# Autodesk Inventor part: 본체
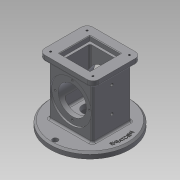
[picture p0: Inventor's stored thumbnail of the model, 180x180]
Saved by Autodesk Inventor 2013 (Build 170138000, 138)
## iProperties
Created: 2019-08
Part Number: 본체
Material: 일반
Document SubType Name: Modeling
Designer: Administrator
Density: 1 g/cm^3
Author: Administrator
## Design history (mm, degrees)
node "작업 평면1"
sketch "스케치1"
  geometry: C1 r 67.5 at (0, 0); 1 further point
  constraints: 1 centre point, 1 coincident
  dimensions: "d1" = 135 diameter of C1
extrude "돌출1" new body sketch "스케치1" distance "d2" = 10; taper "d3" = 0 deg
sketch "스케치2"
  geometry: L1 (-37, -33)-(37, -33); L2 (37, -33)-(37, 33); L3 (37, 33)-(-37, 33); L4 (-37, 33)-(-37, -33); L5 (-37, -33)-(37, 33); L6 (37, -33)-(-37, 33); C1 r 67.5 at (0, 0) reference
  constraints: 12 end point, 2 midpoint, 2 parallel, 1 horizontal, 1 perpendicular
  dimensions: "d4" = 74 distance of L2.end L3.end; "d6" = 66 distance of L1.end L2.end
extrude "돌출2" join sketch "스케치2" distance "d7" = 88; taper "d8" = 0 deg
sketch "스케치3"
  geometry: L1 (-46, -41)-(46, -41); L2 (46, -41)-(46, 41); L3 (46, 41)-(-46, 41); L4 (-46, 41)-(-46, -41); L5 (-46, -41)-(46, 41); L6 (46, -41)-(-46, 41); 1 further point
  constraints: 12 end point, 2 midpoint, 2 parallel, 1 horizontal, 1 perpendicular
  dimensions: "d9" = 92 distance of L2.end L3.end; "d11" = 82 distance of L1.end L2.end
extrude "돌출3" join sketch "스케치3" distance "d12" = 10; taper "d13" = 0 deg
sketch "스케치4"
  geometry: C1 r 35 at (37, 44); 1 further point
  constraints: 1 centre point, 1 coincident
  dimensions: "d14" = 70 diameter of C1
extrude "돌출4" cut sketch "스케치4" distance "d15" = 3; taper "d16" = 0 deg
sketch "스케치5"
  geometry: C1 r 35 at (0, 0) reference; C2 r 24 at (0, 0)
  constraints: 1 centre point, 1 coincident
  dimensions: "d17" = 48 diameter of C2
extrude "돌출5" cut sketch "스케치5" stored distance "d18" = 3; taper "d19" = 0 deg
sketch "스케치6"
  geometry: C1 r 24 at (37, -44) reference; C2 r 35 at (37, -44)
  constraints: 1 centre point, 1 coincident
  dimensions: "d20" = 70 diameter of C2
extrude "돌출6" cut sketch "스케치6" distance "d21" = 3; taper "d22" = 0 deg
sketch "스케치7"
  geometry: L1 (-26, -26)-(26, -26); L2 (26, -26)-(26, 26); L3 (26, 26)-(-26, 26); L4 (-26, 26)-(-26, -26); L5 (-26, -26)-(26, 26); L6 (26, -26)-(-26, 26); 1 further point
  constraints: 12 end point, 2 midpoint, 2 parallel, 1 horizontal, 1 perpendicular
  dimensions: "d23" = 52 distance of L2.end L3.end; "d25" = 52 distance of L1.end L2.end
extrude "돌출7" cut sketch "스케치7" distance "d26" = 8; taper "d27" = 0 deg
sketch "스케치8"
  geometry: L1 (-22, -22)-(22, -22); L2 (22, -22)-(22, 22); L3 (22, 22)-(-22, 22); L4 (-22, 22)-(-22, -22); L5 (-22, -22)-(22, 22); L6 (22, -22)-(-22, 22); 1 further point
  constraints: 12 end point, 2 midpoint, 2 parallel, 1 horizontal, 1 perpendicular
  dimensions: "d28" = 44 distance of L2.end L3.end; "d30" = 44 distance of L1.end L2.end
extrude "돌출8" cut sketch "스케치8" distance "d31" = 74; taper "d32" = 0 deg
sketch "스케치9"
  geometry: C1 r 67.5 at (0, 0) reference; C2 r 25 at (0, 0)
  constraints: 1 centre point, 1 coincident
  dimensions: "d33" = 50 diameter of C2
extrude "돌출9" cut sketch "스케치9" distance "d34" = 18; taper "d35" = 0 deg
sketch "스케치10"
  geometry: C1 r 25 at (0, 0) reference; C2 r 12.5 at (0, 0)
  constraints: 1 centre point, 1 coincident
  dimensions: "d36" = 25 diameter of C2
extrude "돌출10" cut sketch "스케치10" distance "d37" = 18; taper "d38" = 0 deg
sketch "스케치11"
  geometry: C1 r 67.5 at (0, 0) reference; C2 r 4.5 at (0, 59); C3 r 4.5 at (-59, 0); C4 r 4.5 at (0, -59); A1 r 59 centre (0, 0) between (0, 59) and (-59, 0)
  constraints: 4 centre point, 3 point on circle, 2 vertical alignment, 1 coincident, 1 horizontal alignment
  dimensions: "d39" = 118 diameter of A1; "d40" = 9 diameter of C2; "d41" = 9 diameter of C3; "d42" = 9 diameter of C4
extrude "돌출11" cut sketch "스케치11" stored distance "d43" = 18; taper "d44" = 0 deg
sketch "스케치12"
  geometry: L1 (10, -34.5)-(10, 100.5) reference; 3 further points
  constraints: 2 horizontal alignment
  dimensions: "d45" = 37 distance from line of point (-27, 33) L1; "d46" = 43 distance of point (-70, 33) point (-27, 33)
hole "구멍1" sketch "스케치12" at (-70, 33), (-27, 33) diameter "d47" = 4.917; stored, may be unused: countersink angle "d51" = 90 deg, drill point angle "d53" = 0 deg; dims "d48" = 6, "d49" = 4, "d50" = 2, "d52" = 28
fillet "모깎기1" dims "d60" = 10
sketch "스케치16"
  geometry: A1 r 10 centre (-36, 31) between (-36, 41) and (-46, 31) reference; A2 r 10 centre (-36, -31) between (-46, -31) and (-36, -41) reference; A3 r 10 centre (36, -31) between (36, -41) and (46, -31) reference; A4 r 10 centre (36, 31) between (46, 31) and (36, 41) reference; 1 further point
hole "구멍2" sketch "스케치16" at (-36, 31), (36, 31), (36, -31), (-36, -31) diameter "d61" = 3.242; stored, may be unused: countersink angle "d65" = 90 deg, drill point angle "d67" = 118 deg; dims "d62" = 4, "d63" = 4, "d64" = 2, "d66" = 6
sketch "스케치17" dims "d68" = 58
  geometry: C1 r 24 at (0, 0) reference; C2 r 35 at (0, 0) reference; 2 further points
  constraints: 2 vertical alignment, 1 coincident, 2 other
hole "구멍3" sketch "스케치17" at (0, 29) diameter "d70" = 3.242; stored, may be unused: countersink angle "d74" = 90 deg, drill point angle "d76" = 118 deg; dims "d71" = 4, "d72" = 4, "d73" = 2, "d75" = 6
node "작업 평면2"
node "작업 평면4"
sketch "스케치18"
  geometry: C1 r 59 at (0, 0); 1 further point
  constraints: 1 centre point, 1 coincident, 1 other
  dimensions: "d82" = 118 diameter of C1
feature "엠보싱1" sketch "스케치18" dims "d1" = 135, "d9" = 92, "d11" = 82, "d83" = 0.5, "d84" = 0
chamfer "모따기1" distance "d85" = 3; stored, may be unused: second distance "d86" = 2, angle "d87" = 45 deg
chamfer "모따기2" distance "d88" = 1; stored, may be unused: second distance "d89" = 2, angle "d90" = 45 deg
fillet "모깎기2" dims "d91" = 3
fillet "모깎기3" dims "d92" = 3
fillet "모깎기4" dims "d93" = 3
fillet "모깎기5" dims "d94" = 3
fillet "모깎기6" dims "d95" = 3
fillet "모깎기7" dims "d96" = 3
node "솔리드1"
pattern_circular "원형 패턴1" dims angle "d78" = 360 deg
mirror "대칭1"
other parameters: "d0" = -54, "d81" = 31
